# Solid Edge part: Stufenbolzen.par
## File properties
Author: helmut
Template: Normal.par
Last saved by: helmut
Revision: 3
Application: Solid Edge
Teilflächenrmatvorlage: Model Default
Coef. of Thermal Exp: 0.0
Thermal Conductivity: 0.0
Specific Heat: 0.0
Modulus of Elasticity: 0.0
Poission's Ratio: 0.0
Yield Stress: 0.0
Ultimate Stress: 0.0
Elongation: 0.0
Dichte: 7,79999702546 kg/dm^3
Genauigkeit: 0,010
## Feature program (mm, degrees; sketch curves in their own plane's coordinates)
sketch for "unnamed RevolvedProtrusion 1" plane through (0, 0, 0) normal (0, -1, 0) x-axis (1, 0, 0)
  line (0, 19.5701) -> (5, 19.5701)
  line (5, 19.5701) -> (5, 11.5701)
  line (5, 11.5701) -> (3, 11.5701)
  line (3, 11.5701) -> (3, -10.4299)
  line (3, -10.4299) -> (0, -10.4299)
  dimension (linear) = 3
  dimension (linear) = 3
revolve "unnamed RevolvedProtrusion 1" add finite 360 deg about sketch line (0, -10.4299) -> (0, 19.5701)
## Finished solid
Body 1: solid body, 5 faces, 4 edges, 0 vertices.
  Faces by surface: plane 3, cylinder 2
  Edges by curve: circle 4
Bounding box of the edges (mm): 10.000 x 10.000 x 30.000, from (-5, -5, -10.4299) to (5, 5, 19.5701).
Cylindrical faces by radius (mm): R3 x1, R5 x1
Planar faces by outward normal: +z 1, -z 2
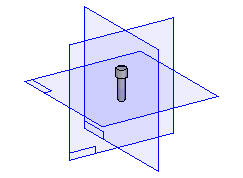
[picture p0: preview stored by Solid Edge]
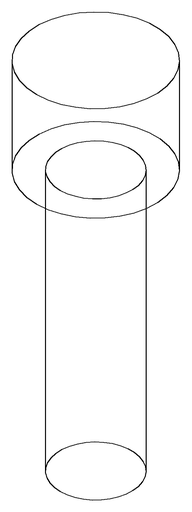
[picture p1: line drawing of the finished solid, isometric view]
